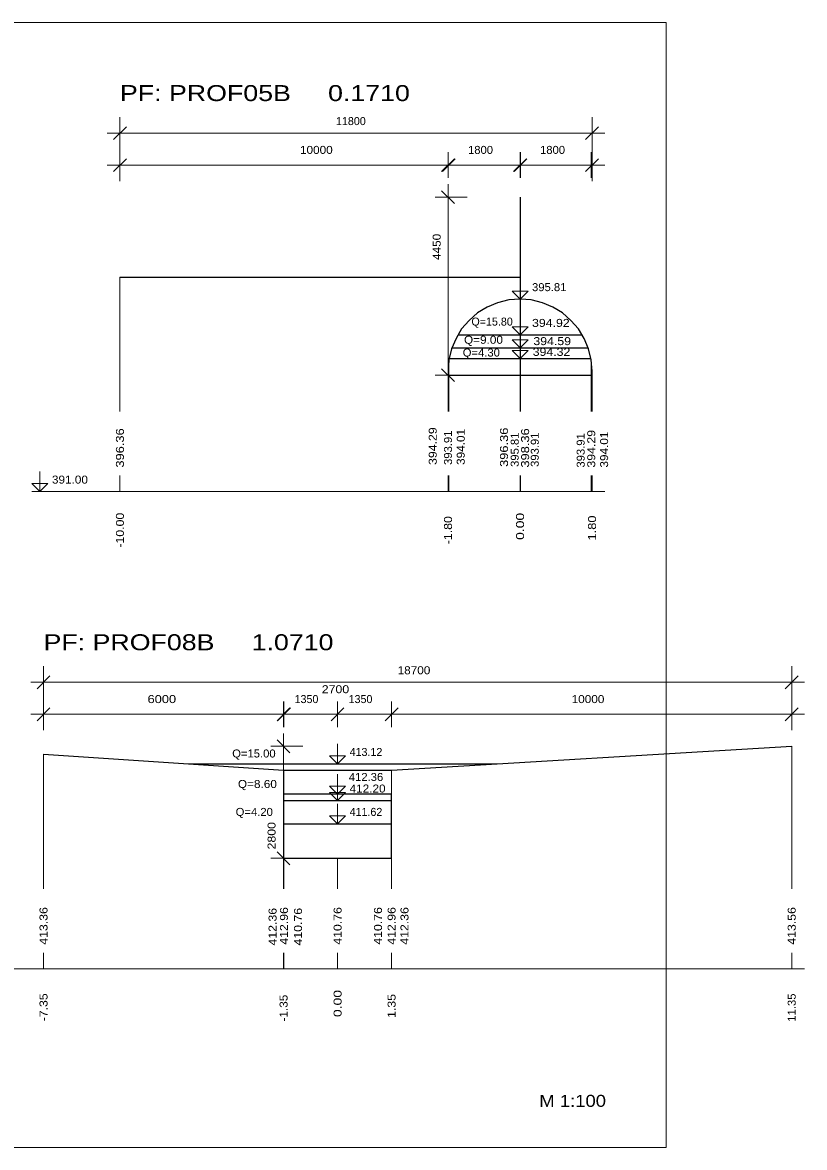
# Model space of a CAD drawing. Extents: x 7 to 442, y -393 to 441.
# Drawn here: x 42.23 to 61.77, y 76.44 to 104.55 of the extents above; entities that cross this region are included whole.
import ezdxf
from ezdxf.enums import TextEntityAlignment as Align

# ---------------------------------------------------------------- set-up
doc = ezdxf.new("R2010")
doc.units = 0
doc.header["$LTSCALE"] = 0.08
doc.layers.add('63', color=7, linetype='Continuous', lineweight=13)
doc.layers.add('7', color=7, linetype='Continuous', lineweight=13)

msp = doc.modelspace()

# ---------------------------------------------------------------- linework, layer by layer
at = {"layer": '63'}
msp.add_lwpolyline([(17.844, 76.435), (17.844, 104.551), (38.081, 104.551), (58.318, 104.551), (58.318, 76.435), (38.081, 76.435)], close=True, dxfattribs=at)
at = {"layer": '7'}
for p, q in [((44.662, 100.587), (44.662, 102.187)), ((56.462, 100.587), (56.462, 102.187)), ((44.342, 101.787), (56.782, 101.787)), ((44.502, 101.627), (44.822, 101.947)), ((56.302, 101.627), (56.622, 101.947)), ((44.662, 100.667), (44.662, 101.307)), ((52.862, 100.667), (52.862, 101.307)), ((52.862, 100.667), (52.862, 101.307)), ((54.662, 100.667), (54.662, 101.307)), ((54.662, 100.667), (54.662, 101.307)), ((54.662, 100.667), (54.662, 101.307)), ((54.672, 100.667), (54.672, 101.307)), ((54.672, 100.667), (54.672, 101.307)), ((56.442, 100.667), (56.442, 101.307)), ((56.462, 100.667), (56.462, 101.307)), ((56.462, 100.667), (56.462, 101.307)), ((44.342, 100.987), (56.782, 100.987)), ((44.502, 100.827), (44.822, 101.147)), ((52.702, 100.827), (53.022, 101.147)), ((52.702, 100.827), (53.022, 101.147)), ((52.722, 100.827), (53.042, 101.147)), ((54.502, 100.827), (54.822, 101.147)), ((54.502, 100.827), (54.822, 101.147)), ((54.502, 100.827), (54.822, 101.147)), ((54.512, 100.827), (54.832, 101.147)), ((54.512, 100.827), (54.832, 101.147)), ((56.302, 100.827), (56.622, 101.147)), ((56.302, 100.827), (56.622, 101.147)), ((52.862, 95.577), (52.862, 100.507)), ((52.542, 100.187), (53.342, 100.187)), ((53.022, 100.027), (52.702, 100.347)), ((54.672, 94.827), (54.672, 100.187)), ((44.662, 94.827), (44.662, 98.187)), ((54.662, 94.827), (54.662, 98.187)), ((54.662, 94.827), (54.662, 97.637)), ((54.662, 97.637), (54.672, 97.637)), ((54.672, 94.827), (54.672, 97.637)), ((53.022, 95.577), (52.702, 95.897)), ((52.882, 94.827), (52.882, 96.117)), ((56.442, 94.827), (56.442, 96.117)), ((52.542, 95.737), (53.342, 95.737)), ((52.862, 94.827), (52.862, 95.837)), ((52.862, 94.827), (52.862, 95.737)), ((54.662, 94.827), (54.662, 95.737)), ((56.462, 94.827), (56.462, 95.837)), ((56.462, 94.827), (56.462, 95.737)), ((44.662, 92.827), (44.662, 93.227)), ((52.862, 92.827), (52.862, 93.227)), ((52.862, 92.827), (52.862, 93.227)), ((52.882, 92.827), (52.882, 93.227)), ((54.662, 92.827), (54.662, 93.227)), ((54.662, 92.827), (54.662, 93.227)), ((54.662, 92.827), (54.662, 93.227)), ((54.672, 92.827), (54.672, 93.227)), ((54.672, 92.827), (54.672, 93.227)), ((56.442, 92.827), (56.442, 93.227)), ((56.462, 92.827), (56.462, 93.227)), ((56.462, 92.827), (56.462, 93.227)), ((42.462, 92.827), (56.782, 92.827)), ((42.752, 86.862), (42.752, 88.462)), ((61.452, 86.862), (61.452, 88.462)), ((42.432, 88.062), (61.772, 88.062)), ((42.592, 87.902), (42.912, 88.222)), ((61.292, 87.902), (61.612, 88.222)), ((42.752, 86.942), (42.752, 87.582)), ((48.752, 86.942), (48.752, 87.582)), ((48.752, 86.942), (48.752, 87.582)), ((48.762, 86.942), (48.762, 87.582)), ((48.762, 86.942), (48.762, 87.582)), ((50.102, 86.942), (50.102, 87.582)), ((51.452, 86.942), (51.452, 87.582)), ((51.452, 86.942), (51.452, 87.582)), ((51.452, 86.942), (51.452, 87.582)), ((61.452, 86.942), (61.452, 87.582)), ((42.432, 87.262), (61.772, 87.262)), ((42.592, 87.102), (42.912, 87.422)), ((48.592, 87.102), (48.912, 87.422)), ((48.592, 87.102), (48.912, 87.422)), ((48.602, 87.102), (48.922, 87.422)), ((48.602, 87.102), (48.922, 87.422)), ((49.942, 87.102), (50.262, 87.422)), ((51.292, 87.102), (51.612, 87.422)), ((51.292, 87.102), (51.612, 87.422)), ((51.292, 87.102), (51.612, 87.422)), ((61.292, 87.102), (61.612, 87.422)), ((48.912, 86.302), (48.592, 86.622)), ((48.752, 83.502), (48.752, 86.782)), ((48.432, 86.462), (49.232, 86.462)), ((61.452, 82.902), (61.452, 86.462)), ((42.752, 82.902), (42.752, 86.262)), ((48.752, 82.902), (48.752, 85.862)), ((48.762, 82.902), (48.762, 85.862)), ((51.452, 82.902), (51.452, 85.862)), ((48.752, 85.262), (48.762, 85.262)), ((48.762, 82.902), (48.762, 85.262)), ((51.452, 82.902), (51.452, 85.262)), ((48.912, 83.502), (48.592, 83.822)), ((48.432, 83.662), (49.232, 83.662)), ((48.752, 82.902), (48.752, 83.662)), ((50.102, 82.902), (50.102, 83.662)), ((51.452, 82.902), (51.452, 83.662)), ((42.752, 80.902), (42.752, 81.302)), ((48.752, 80.902), (48.752, 81.302)), ((48.752, 80.902), (48.752, 81.302)), ((48.762, 80.902), (48.762, 81.302)), ((48.762, 80.902), (48.762, 81.302)), ((50.102, 80.902), (50.102, 81.302)), ((51.452, 80.902), (51.452, 81.302)), ((51.452, 80.902), (51.452, 81.302)), ((51.452, 80.902), (51.452, 81.302)), ((61.452, 80.902), (61.452, 81.302)), ((40.552, 80.902), (61.772, 80.902))]:
    msp.add_line(p, q, dxfattribs=at)
at = {"layer": '7', "lineweight": 25}
for p, q in [((53.112, 96.743), (56.212, 96.743)), ((52.962, 96.422), (56.362, 96.422)), ((52.891, 96.152), (56.433, 96.152)), ((46.382, 86.02), (54.086, 86.02)), ((48.752, 85.106), (51.452, 85.106)), ((48.752, 84.522), (51.452, 84.522))]:
    msp.add_line(p, q, dxfattribs=at)
for points in [[(44.662, 98.187), (54.662, 98.187), (54.662, 97.637), (54.382, 97.617), (54.102, 97.547), (53.842, 97.437), (53.602, 97.297), (53.392, 97.107), (53.202, 96.897), (53.062, 96.657), (52.952, 96.397), (52.882, 96.117), (52.862, 95.837), (52.862, 95.737), (54.662, 95.737), (56.462, 95.737), (56.462, 95.837), (56.442, 96.117), (56.372, 96.397), (56.262, 96.657), (56.122, 96.897), (55.932, 97.107), (55.722, 97.297), (55.482, 97.437), (55.222, 97.547), (54.942, 97.617), (54.672, 97.637), (54.672, 100.187)], [(42.752, 86.262), (48.752, 85.862), (48.752, 83.662), (50.102, 83.662), (51.452, 83.662), (51.452, 85.262), (48.762, 85.262), (48.762, 85.862), (51.452, 85.862), (61.452, 86.462)]]:
    msp.add_lwpolyline(points, dxfattribs=at)
at = {"layer": '7'}
for points in [[(54.662, 98.137), (54.662, 97.637), (54.462, 97.837), (54.862, 97.837), (54.662, 97.637)], [(54.662, 97.243), (54.662, 96.743), (54.462, 96.943), (54.862, 96.943), (54.662, 96.743)], [(54.662, 96.922), (54.662, 96.422), (54.462, 96.622), (54.862, 96.622), (54.662, 96.422)], [(54.662, 96.652), (54.662, 96.152), (54.462, 96.352), (54.862, 96.352), (54.662, 96.152)], [(42.662, 93.327), (42.662, 92.827), (42.462, 93.027), (42.862, 93.027), (42.662, 92.827)], [(50.102, 86.52), (50.102, 86.02), (49.902, 86.22), (50.302, 86.22), (50.102, 86.02)], [(50.102, 85.762), (50.102, 85.262), (49.902, 85.462), (50.302, 85.462), (50.102, 85.262)], [(50.102, 85.606), (50.102, 85.106), (49.902, 85.306), (50.302, 85.306), (50.102, 85.106)], [(50.102, 85.022), (50.102, 84.522), (49.902, 84.722), (50.302, 84.722), (50.102, 84.522)]]:
    msp.add_lwpolyline(points, dxfattribs=at)

# ---------------------------------------------------------------- texts
at = {"layer": '63', "width": 1.15}
msp.add_text('M 1:100', height=0.3, dxfattribs=at).set_placement((55.977, 77.451), align=Align.CENTER)
at = {"layer": '7'}
for s, height, width, p in [('PF: PROF05B     0.1710', 0.4, 1.25, (44.662, 102.587)), ('10000', 0.2, 1.1, (49.162, 101.267)), ('1800', 0.2, 1.05, (53.362, 101.267)), ('1800', 0.2, 1.05, (55.162, 101.267)), ('395.81', 0.2, 1.05, (54.962, 97.837)), ('394.92', 0.2, 1.15, (54.962, 96.943)), ('Q=9.00', 0.2, 1.1, (53.262, 96.522)), ('394.59', 0.2, 1.15, (54.995, 96.488)), ('Q=4.30', 0.2, 1.05, (53.23, 96.202)), ('394.32', 0.2, 1.15, (54.979, 96.219)), ('391.00', 0.2, 1.1, (42.962, 93.027)), ('PF: PROF08B     1.0710', 0.4, 1.25, (42.752, 88.862)), ('18700', 0.2, 1.1, (51.602, 88.262)), ('6000', 0.2, 1.2, (45.352, 87.542)), ('2700', 0.2, 1.15, (49.707, 87.788)), ('10000', 0.2, 1.1, (55.952, 87.542)), ('Q=15.00', 0.2, 1.05, (47.468, 86.182)), ('412.36', 0.2, 1.05, (50.383, 85.595)), ('Q=8.60', 0.2, 1.1, (47.611, 85.42)), ('412.20', 0.2, 1.1, (50.402, 85.306)), ('Q=4.20', 0.2, 1.05, (47.555, 84.722))]:
    msp.add_text(s, height=height, dxfattribs=dict(at, width=width)).set_placement(p)
for s, p in [('11800', (50.062, 101.987)), ('Q=15.80', (53.447, 96.976)), ('1350', (49.027, 87.542)), ('1350', (50.377, 87.542)), ('413.12', (50.402, 86.22)), ('411.62', (50.402, 84.722))]:
    msp.add_text(s, height=0.2, dxfattribs=at).set_placement(p)
for s, width, p in [('4450', 1.1, (52.679, 98.616)), ('396.36 ', 1.2, (44.762, 93.427)), ('394.29 ', 1.15, (52.58, 93.493)), ('393.91 ', 1.05, (52.962, 93.493)), ('394.01 ', 1.1, (53.28, 93.494)), ('396.36 ', 1.2, (54.361, 93.444)), ('395.81 ', 1.05, (54.629, 93.444)), ('398.36 ', 1.2, (54.889, 93.427)), ('393.91 ', 1.05, (55.13, 93.444)), ('393.91 ', 1.05, (56.278, 93.427)), ('394.29 ', 1.15, (56.542, 93.427)), ('394.01 ', 1.1, (56.863, 93.427)), ('-10.00 ', 1.15, (44.762, 91.427)), ('  0.00 ', 1.3, (54.762, 91.427)), ('  0.00 ', 1.3, (54.762, 91.427)), ('  0.00 ', 1.3, (54.762, 91.427)), (' -1.80 ', 1.15, (52.962, 91.427)), (' -1.80 ', 1.15, (52.962, 91.427)), ('  1.80 ', 1.2, (56.562, 91.427)), ('  1.80 ', 1.2, (56.562, 91.427)), ('2800', 1.15, (48.552, 83.884)), ('413.36 ', 1.15, (42.852, 81.502)), ('412.36 ', 1.15, (48.577, 81.483)), ('412.96 ', 1.15, (48.862, 81.502)), ('410.76 ', 1.15, (49.212, 81.483)), ('410.76 ', 1.15, (50.202, 81.502)), ('410.76 ', 1.15, (51.211, 81.502)), ('412.96 ', 1.15, (51.552, 81.502)), ('412.36 ', 1.15, (51.874, 81.502)), ('413.56 ', 1.15, (61.552, 81.502)), (' -7.35 ', 1.15, (42.852, 79.502)), (' -1.35 ', 1.1, (48.852, 79.502)), (' -1.35 ', 1.1, (48.852, 79.502)), ('  0.00 ', 1.3, (50.202, 79.502)), ('  1.35 ', 1.15, (51.552, 79.502)), ('  1.35 ', 1.15, (51.552, 79.502)), ('  1.35 ', 1.15, (51.552, 79.502)), (' 11.35 ', 1.05, (61.552, 79.502))]:
    msp.add_text(s, height=0.2, rotation=90, dxfattribs=dict(at, width=width)).set_placement(p)

doc.saveas('drawing.dxf')
